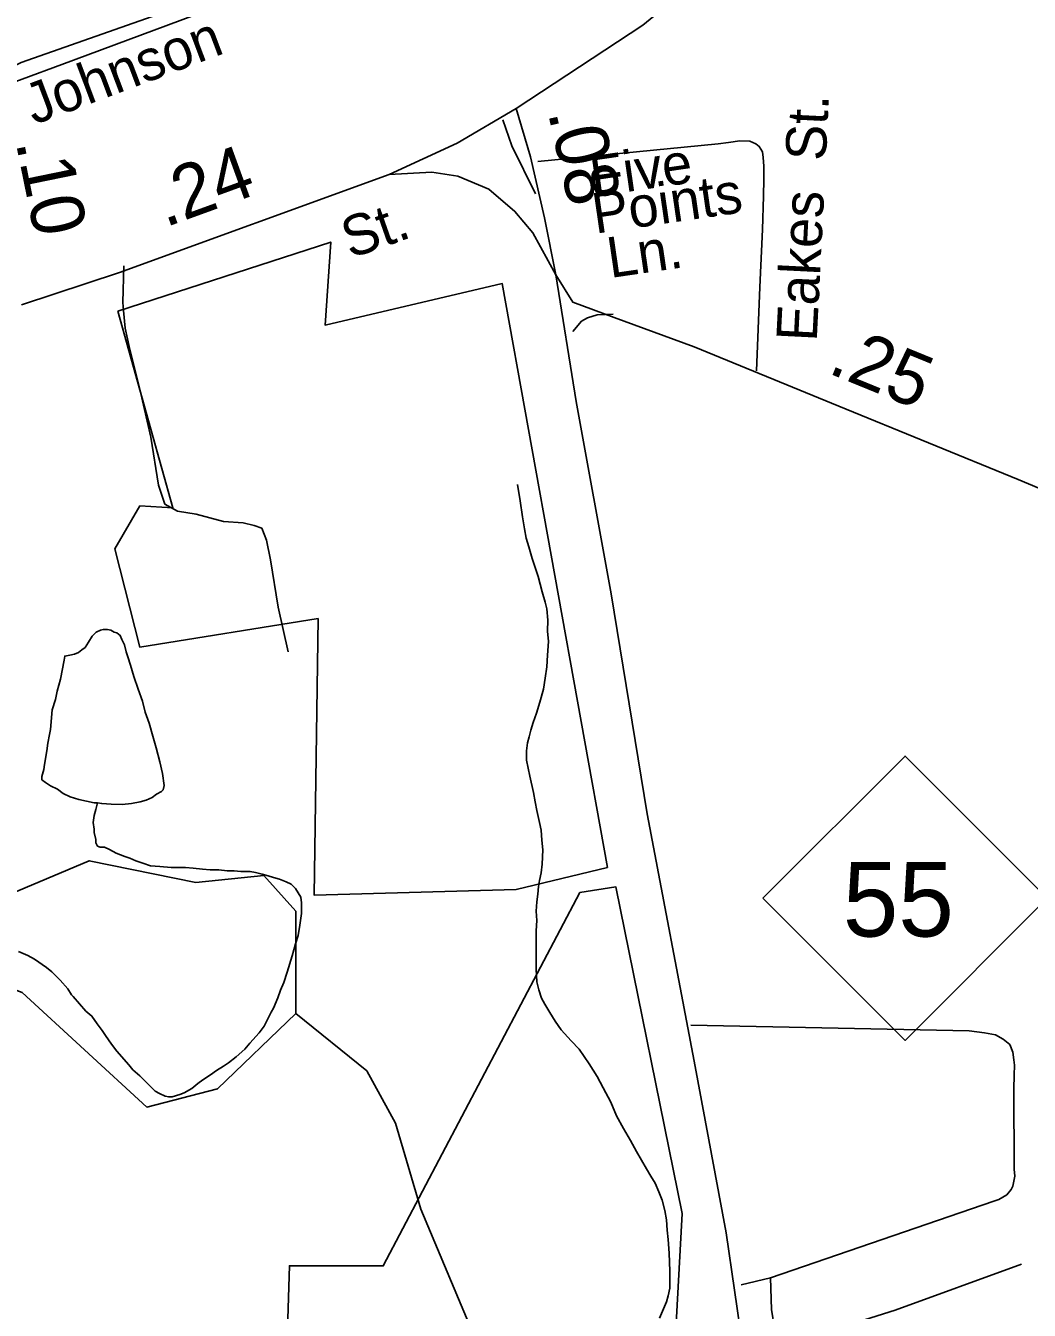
# Model space of a CAD drawing. Extents: x 2001466 to 2224147, y 644118 to 847247.
# Drawn here: x 2070436 to 2072789, y 669407 to 672416 of the extents above; entities that cross this region are included whole.
import ezdxf

# ---------------------------------------------------------------- set-up
doc = ezdxf.new("R2010")
doc.units = 0
for name, color, linetype in [('Exist Boundary Political City Limit New', 7, 'Continuous'), ('Exist Hydrographic Misc Water Feature', 7, 'Continuous'), ('Exist Railroad Mainline', 7, 'Continuous'), ('Exist Road Non-System Type 51', 7, 'Continuous'), ('Exist Road Non-System Type 51 Label', 7, 'Continuous'), ('Exist Road Primary NC Attributed', 7, 'Continuous'), ('Exist Road Primary NC Service Mileage Hundredths English Label', 7, 'Continuous'), ('Exist Road Primary NC Shield CELL', 7, 'Continuous'), ('Exist Road Primary NC Shield Number Label', 7, 'Continuous'), ('Exist Road Primary US Attributed', 7, 'Continuous'), ('Exist Road Primary US Label', 7, 'Continuous'), ('Exist Road Primary US Mileage Hundredths English Label', 7, 'Continuous'), ('Exist Road Primary US UnDivided 4 Lane Attributed', 7, 'Continuous'), ('Exist Road Secondary Mileage Hundredths English Label', 7, 'Continuous'), ('Exist Road Secondary Type 51 Attributed', 7, 'Continuous'), ('Exist Road Secondary Type 51 Label', 7, 'Continuous'), ('Map Preparation Boundary City Limit Buffer Line', 7, 'Continuous')]:
    doc.layers.add(name, color=color, linetype=linetype)

msp = doc.modelspace()

# ---------------------------------------------------------------- linework, layer by layer
at = {"layer": 'Exist Boundary Political City Limit New'}
for points in [[(2070651.9, 671747.6), (2070781.5, 671287.2), (2070704.1, 671291.5), (2070645.2, 671190.5), (2070703.8, 670960.8), (2071121.6, 671027.6), (2071112.4, 670379.5), (2071585.9, 670392.5), (2071799.9, 670444.4), (2071553.4, 671812.4), (2071138.2, 671715.2), (2071151.2, 671909.7), (2070651.9, 671747.6)], [(2071735, 670386), (2071274.5, 669510.7), (2071054.4, 669511.2), (2071028.9, 668687.9), (2071923.1, 668674.3), (2071975, 669633.9), (2071819.4, 670399), (2071735, 670386)]]:
    msp.add_lwpolyline(points, dxfattribs=at)
at = {"layer": 'Exist Hydrographic Misc Water Feature'}
for points in [[(2071589.1, 671341.9), (2071595.1, 671303.6), (2071601, 671265.8), (2071605.3, 671237.6), (2071609.4, 671215.9), (2071615.4, 671195.9), (2071623.4, 671167.9), (2071637.7, 671126), (2071647.3, 671090), (2071653.7, 671066), (2071657.8, 671050), (2071659.9, 671024.1), (2071659.7, 670997.7), (2071661.7, 670973.9), (2071659.7, 670941.7), (2071657.6, 670914.1), (2071653.7, 670887.9), (2071649.8, 670861.8), (2071641.8, 670831.7), (2071634, 670805.7), (2071626.2, 670783.8), (2071620.1, 670765.7), (2071616.2, 670750), (2071612.3, 670736), (2071610, 670717.7), (2071610.2, 670695.8), (2071618.4, 670658.1), (2071626.4, 670619.9), (2071630.3, 670597.8), (2071634.4, 670578.1), (2071640.8, 670550), (2071644.5, 670532), (2071646.5, 670508.2), (2071648.8, 670485.9), (2071646.9, 670452.1), (2071644.9, 670432.1), (2071640.6, 670414.1), (2071638.7, 670399.8), (2071636.5, 670381.9), (2071634.8, 670363.9), (2071632.8, 670341.9), (2071634.6, 670320.1), (2071632.8, 670296.1), (2071632.8, 670268.1), (2071633.2, 670242.1), (2071633, 670227.9), (2071633.2, 670206), (2071634.8, 670176.1), (2071639.1, 670158), (2071645.1, 670138), (2071653.5, 670124.2), (2071665, 670104.2), (2071677.5, 670084.1), (2071691.4, 670064.1), (2071715.2, 670038.2), (2071733.7, 670018.4), (2071757.3, 669984.4), (2071775.7, 669954.4), (2071789.7, 669928.4), (2071807.7, 669894.4), (2071821.4, 669862.3), (2071837.8, 669832.7), (2071854, 669804.6), (2071868, 669778.6), (2071879.9, 669758.5), (2071891.8, 669738.5), (2071902, 669720.7), (2071911.7, 669704.7), (2071920.3, 669684.7), (2071928.1, 669664.8), (2071934.2, 669640.8), (2071938.1, 669618.7), (2071940.2, 669594.9), (2071942.4, 669572.6), (2071944.3, 669540.7), (2071946.3, 669498.6), (2071946.5, 669474.6), (2071946.3, 669458.9), (2071942.6, 669440.8), (2071938.5, 669426.8), (2071922.3, 669388.7)], [(2070604.5, 670595.9), (2070614.7, 670594), (2070636.6, 670592.3), (2070662.5, 670592), (2070684.6, 670594.3), (2070704.3, 670598.2), (2070718.7, 670602.1), (2070732.8, 670608.1), (2070742.7, 670616.3), (2070754.6, 670622.2), (2070758.2, 670626.2), (2070760.5, 670636.4), (2070756.6, 670664.2), (2070750.7, 670692.2), (2070742.2, 670724.3), (2070734.3, 670752.3), (2070726.1, 670782.3), (2070716.4, 670808.1), (2070710.1, 670834.2), (2070700.2, 670862.1), (2070690, 670892), (2070682, 670918), (2070676, 670938), (2070671.9, 670949.9), (2070667.8, 670965.9), (2070661.9, 670978.2), (2070658, 670988.1), (2070650, 670994.2), (2070644, 670995.9), (2070635.6, 671000), (2070628, 671002), (2070618.2, 671001.9), (2070611.8, 671000), (2070601.8, 670995.8), (2070597.9, 670992), (2070592.2, 670985.9), (2070583.7, 670971.8), (2070579.8, 670965.9), (2070576, 670960), (2070568.2, 670953.9), (2070559.8, 670947.8), (2070550.3, 670944), (2070540.1, 670941.9), (2070528, 670939.7), (2070526.3, 670929.8), (2070517.9, 670885.6), (2070509.9, 670857.7), (2070506.2, 670837.9), (2070498.4, 670813.6), (2070494.5, 670767.9), (2070492.1, 670755.7), (2070488.4, 670735.6), (2070486.1, 670717.7), (2070480.4, 670685.7), (2070478.6, 670673.8), (2070474.5, 670657.8), (2070474.5, 670649.7), (2070482.4, 670643.7), (2070494.5, 670635.7), (2070510.7, 670628), (2070524.5, 670617.8), (2070540.5, 670610.1), (2070560.8, 670603.8), (2070578.8, 670599.8), (2070596.9, 670595.9), (2070604.5, 670595.9)], [(2070604.5, 670595.9), (2070600.6, 670579.9), (2070596.5, 670565.9), (2070594.6, 670549.9), (2070596.7, 670533.8), (2070597.1, 670526.1), (2070600.8, 670510.1), (2070600.8, 670502), (2070604.9, 670494.1)], [(2071041.4, 670174.8), (2071049.2, 670198.8), (2071061.1, 670237.1), (2071069.1, 670265.1), (2071075, 670284.9), (2071078.9, 670309), (2071082.8, 670336.8), (2071083, 670361.1), (2071081, 670374.8), (2071068.7, 670395), (2071058.9, 670405), (2071047.2, 670410.8), (2071031.2, 670416.9), (2071016.8, 670420.7), (2071004.9, 670424.9), (2070990.6, 670428.7), (2070974.8, 670432.8), (2070962.7, 670434.5), (2070940.5, 670434.7), (2070924.7, 670436.7), (2070908.5, 670436.7), (2070888.9, 670438.4), (2070868.6, 670438.7), (2070850.5, 670440.6), (2070828.8, 670442.3), (2070810.9, 670444.6), (2070796.8, 670444.3), (2070776.9, 670444.4), (2070750.9, 670446.4), (2070729.1, 670448.4), (2070710.9, 670454.4), (2070694.5, 670460.2), (2070680.7, 670466.3), (2070668.8, 670470.1), (2070648.5, 670478.1), (2070633, 670486.2), (2070620.7, 670492.1), (2070611, 670491.9), (2070604.9, 670494.1)], [(2071069.3, 670102.3), (2071069.3, 670341.8), (2070994.3, 670425.3), (2070835.3, 670408.8), (2070585.2, 670459.9), (2070385.3, 670375.3), (2070186.4, 670340), (2070152.3, 670307.9), (2070186.4, 670241.6), (2070428.3, 670151.4), (2070720.3, 669883), (2070886.2, 669925.5), (2071069.3, 670102.3)], [(2070419.3, 670247.6), (2070441, 670237.8), (2070457.2, 670229.7), (2070485.3, 670210), (2070497.2, 670200.1), (2070507.5, 670190), (2070517.3, 670180), (2070535.1, 670159.9), (2070543.6, 670146), (2070547.5, 670142.2), (2070577.6, 670108), (2070591.7, 670096.1), (2070603.6, 670078.1), (2070615.3, 670062.1), (2070623.5, 670050.3), (2070637.7, 670030.3), (2070649.6, 670014.3), (2070677.7, 669982.1), (2070687.7, 669970.5), (2070703.5, 669956.3), (2070719.7, 669940.5), (2070729.9, 669930.4), (2070739.6, 669920.4), (2070749.6, 669914.4), (2070763.6, 669908.6), (2070771.8, 669906.6), (2070780, 669906.6), (2070797.8, 669912.4), (2070807.5, 669916.6), (2070825.7, 669926.4), (2070840.1, 669938.4), (2070851.5, 669946.8), (2070869.8, 669958.7), (2070883.7, 669968.7), (2070899.9, 669978.9), (2070911.8, 669986.8), (2070929.5, 670000.7), (2070949.6, 670018.8), (2070961.7, 670032.8), (2070983.4, 670057), (2070995.5, 670072.7), (2071011.5, 670105.1), (2071017.2, 670114.8), (2071027.3, 670138.8), (2071033.2, 670157), (2071041.4, 670174.8)], [(2071504.2, 669253.6), (2071496.2, 669325.9), (2071362.3, 669643.6), (2071303.3, 669844.9), (2071236.2, 669967.6), (2071069.3, 670102.3)]]:
    msp.add_lwpolyline(points, dxfattribs=at)
at = {"layer": 'Exist Railroad Mainline'}
msp.add_lwpolyline([(2070333.9, 672257.2), (2070521.1, 672325.7), (2070893.1, 672463.9), (2071265, 672600.2), (2071643.5, 672725.3), (2071820.5, 672759.8), (2071958.3, 672772.3), (2071981.6, 672773.7), (2072001.4, 672775.2), (2072053.4, 672777.4), (2072102.5, 672778.1), (2072146.5, 672778.1), (2072197.1, 672775.2), (2072218.8, 672774.5), (2072287.7, 672771.5)], dxfattribs=at)
at = {"layer": 'Exist Road Non-System Type 51'}
msp.add_line((2072181.8, 669483), (2072113.5, 669466.4), dxfattribs=at)
for points in [[(2071555, 672195.7), (2071575.8, 672135.3), (2071631.5, 672022.2)], [(2071637, 672098), (2072059.9, 672139.5), (2072083.9, 672143), (2072110, 672146.4), (2072134, 672145.9), (2072147.9, 672139.7), (2072155.7, 672133.5), (2072163.5, 672121.3), (2072165.2, 672107.3), (2072166.8, 672087.3), (2072166.2, 672057.3), (2072165.4, 672017.3), (2072163.8, 671939.3), (2072157, 671803.5), (2072149, 671607.6)], [(2071288.5, 672068.2), (2071388.4, 672073.4), (2071449.1, 672064), (2071522.3, 672033.6), (2071583, 671981.3), (2071624.9, 671931), (2071679.3, 671832.6)], [(2070666, 671853.8), (2070664.3, 671767.8), (2070665.7, 671749.6)], [(2070665.7, 671749.6), (2070669.1, 671707.7), (2070680.1, 671657.5), (2070704.2, 671565), (2070729.9, 671452.5), (2070747.6, 671340.1), (2070762.7, 671295.8), (2070792.4, 671279.2), (2070836.2, 671272.3), (2070899.9, 671255), (2070945.8, 671252.1), (2070971.7, 671245.5), (2070989.5, 671239.2), (2071001, 671211), (2071010, 671164.8), (2071027.8, 671054.4), (2071051.6, 670949.9)], [(2071718.9, 671700.4), (2071739.4, 671724), (2071753.6, 671731.7), (2071775.7, 671739.2), (2071813.7, 671740.4)], [(2071995.8, 670074.7), (2072647.6, 670061.5), (2072683.5, 670056.8), (2072709.4, 670052.3), (2072727.2, 670041.9), (2072742.9, 670029.6), (2072750.5, 670011.4), (2072752.2, 669993.4), (2072753.9, 669981.4), (2072753.4, 669957.4), (2072752.8, 669925.4), (2072753, 669737.4), (2072754.6, 669721.3), (2072750.2, 669697.4), (2072746, 669689.5), (2072735.8, 669677.7), (2072717.5, 669666.1), (2072705.4, 669662.3), (2072181.8, 669483)], [(2072214, 669296.3), (2072242.4, 669315.7), (2072256.6, 669327.4), (2072280.9, 669341), (2072295, 669346.7), (2072313.2, 669354.3), (2072343.4, 669365.7), (2072474.2, 669407), (2072770.4, 669515)], [(2072181.8, 669483), (2072184.3, 669408.9), (2072191.4, 669364.8), (2072194.9, 669340.7), (2072198.4, 669318.6), (2072204.2, 669306.5), (2072214, 669296.3)]]:
    msp.add_lwpolyline(points, dxfattribs=at)
at = {"layer": 'Exist Road Primary NC Attributed'}
for points in [[(2071586.2, 672222.1), (2071619.7, 672109), (2071652.1, 671966.6), (2071679.3, 671832.6)], [(2072296.8, 667169.9), (2072265.9, 667472.6), (2072223, 667941.7), (2072200, 668272.7), (2072152.9, 668949.2), (2072117.3, 669319.9), (2072078.6, 669588), (2072003.2, 669990.2), (2071893.3, 670570.3), (2071808.6, 671085.6), (2071726.9, 671535.9), (2071679.3, 671832.6)], [(2071679.3, 671832.6), (2071718.5, 671768.7), (2071815.9, 671733.1), (2072003.2, 671664), (2072342.2, 671524.7), (2072762.8, 671353), (2073632.4, 670988.6), (2074203.7, 670752), (2074750.5, 670528.9), (2075137.6, 670353), (2075404.5, 670248.8)]]:
    msp.add_lwpolyline(points, dxfattribs=at)
at = {"layer": 'Exist Road Primary NC Shield CELL'}
msp.add_lwpolyline([(2072164.6, 670372.2), (2072497.6, 670705.2), (2072830.6, 670372.2), (2072497.6, 670039.2)], close=True, dxfattribs=at)
at = {"layer": 'Exist Road Primary US Attributed'}
msp.add_lwpolyline([(2070426.2, 671762.6), (2070656, 671838), (2071288.5, 672068.2), (2071447.5, 672141.5), (2071586.2, 672222.1)], dxfattribs=at)
at = {"layer": 'Exist Road Primary US UnDivided 4 Lane Attributed'}
msp.add_lwpolyline([(2071586.2, 672222.1), (2071882.8, 672417.9), (2072046.1, 672552), (2072287.7, 672771.5)], dxfattribs=at)
at = {"layer": 'Exist Road Secondary Type 51 Attributed'}
msp.add_lwpolyline([(2070317.5, 672251.3), (2070340.3, 672289.2), (2070425.5, 672330.3), (2070864.2, 672485), (2071448, 672681.6), (2071971.9, 672866.3), (2072268.5, 672964.2), (2072415.3, 673031.4), (2072577.8, 673164), (2072737.2, 673309.3), (2072781.3, 673391.4), (2072787.7, 673467.2), (2072754.5, 673596.7), (2072710.3, 673786.9)], dxfattribs=at)
at = {"layer": 'Map Preparation Boundary City Limit Buffer Line'}
for points in [[(2070651.9, 671747.6), (2070781.5, 671287.2), (2070704.1, 671291.5), (2070645.2, 671190.5), (2070703.8, 670960.8), (2071121.6, 671027.6), (2071112.4, 670379.5), (2071585.9, 670392.5), (2071799.9, 670444.4), (2071553.4, 671812.4), (2071138.2, 671715.2), (2071151.2, 671909.7), (2070651.9, 671747.6)], [(2071735, 670386), (2071274.5, 669510.7), (2071054.4, 669511.2), (2071028.9, 668687.9), (2071923.1, 668674.3), (2071975, 669633.9), (2071819.4, 670399), (2071735, 670386)]]:
    msp.add_lwpolyline(points, dxfattribs=at)

# ---------------------------------------------------------------- texts
at = {"layer": 'Exist Road Non-System Type 51 Label'}
for s, rotation, p in [('Eakes  St.', 87.1494, (2072290.5, 671675.3)), ('Five', 8.3049, (2071766.3, 672015.2)), ('Points', 8.3049, (2071771.5, 671929)), ('Ln.', 8.3049, (2071806.4, 671825.2))]:
    msp.add_text(s, height=95, rotation=rotation, dxfattribs=at).set_placement(p)
at = {"layer": 'Exist Road Primary NC Service Mileage Hundredths English Label'}
for s, rotation, p in [('.08', 282.8317, (2071660, 672213.5)), ('.25', 337.7924, (2072313.4, 671604))]:
    msp.add_text(s, height=125, rotation=rotation, dxfattribs=at).set_placement(p)
at = {"layer": 'Exist Road Primary NC Shield Number Label'}
msp.add_text('55', height=175, dxfattribs=at).set_placement((2072351.7, 670282.5))
at = {"layer": 'Exist Road Primary US Label'}
msp.add_text(' St.', height=95, rotation=19.3926, dxfattribs=at).set_placement((2071163.9, 671858.4))
at = {"layer": 'Exist Road Primary US Mileage Hundredths English Label'}
msp.add_text('.24', height=125, rotation=19.9972, dxfattribs=at).set_placement((2070762.9, 671943.4))
at = {"layer": 'Exist Road Secondary Mileage Hundredths English Label'}
msp.add_text('.10', height=125, rotation=281.5585, dxfattribs=at).set_placement((2070412.7, 672143.5))
at = {"layer": 'Exist Road Secondary Type 51 Label'}
msp.add_text('Johnson', height=95, rotation=20.6384, dxfattribs=at).set_placement((2070455.9, 672183.6))

doc.saveas('drawing.dxf')
